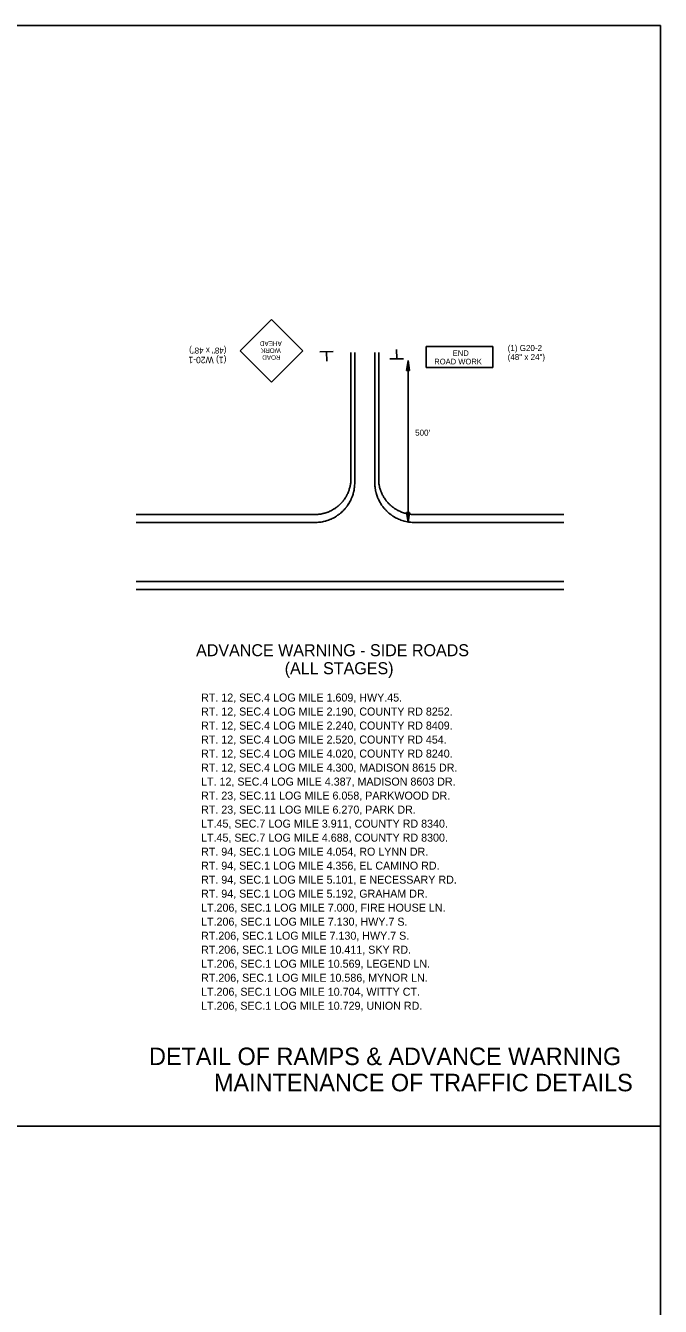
# Model space of a CAD drawing. Extents: x -100 to 745, y -1581 to -107.
# Drawn here: x 281.9 to 345.4, y -278.6 to -150.6 of the extents above; entities that cross this region are included whole.
import ezdxf

# ---------------------------------------------------------------- set-up
doc = ezdxf.new("R2010")
doc.units = 0
for name, color, linetype in [('Default', 7, 'Continuous'), ('R_Contour Annot', 7, 'Continuous'), ('R_Draft', 7, 'Continuous')]:
    doc.layers.add(name, color=color, linetype=linetype)

msp = doc.modelspace()

# ---------------------------------------------------------------- linework, layer by layer
at = {"layer": 'Default'}
for p, q in [((303.41, -183.07), (306.53, -179.95)), ((306.53, -179.95), (309.66, -183.07)), ((319.05, -183.86), (319.04, -182.94)), ((328.64, -182.65), (321.99, -182.65)), ((321.99, -184.74), (321.99, -182.65)), ((328.64, -184.74), (328.64, -182.65)), ((303.41, -183.07), (306.53, -186.2)), ((306.53, -186.2), (309.66, -183.07)), ((311.36, -183.18), (312.71, -183.16)), ((312.04, -183.19), (312.05, -184.11)), ((314.45, -187.09), (314.45, -183.24)), ((314.85, -187.09), (314.85, -183.24)), ((316.85, -187.09), (316.85, -183.24)), ((317.25, -187.09), (317.25, -183.24)), ((319.72, -183.88), (318.37, -183.89)), ((320.03, -185.05), (320.18, -184.05)), ((320.06, -185.05), (320.18, -184.22)), ((320.18, -184.05), (320.18, -200.24)), ((320.33, -185.05), (320.18, -184.05)), ((320.31, -185.05), (320.18, -184.22)), ((320.03, -185.05), (320.33, -185.05)), ((320.08, -185.05), (320.18, -184.39)), ((320.11, -185.05), (320.18, -184.55)), ((320.13, -185.05), (320.18, -184.72)), ((320.16, -185.05), (320.18, -184.89)), ((320.28, -185.05), (320.18, -184.39)), ((320.26, -185.05), (320.18, -184.55)), ((320.23, -185.05), (320.18, -184.72)), ((320.21, -185.05), (320.18, -184.89)), ((328.64, -184.74), (321.99, -184.74)), ((320.03, -199.24), (320.18, -200.24)), ((320.03, -199.24), (320.33, -199.24)), ((320.06, -199.24), (320.18, -200.07)), ((320.08, -199.24), (320.18, -199.9)), ((320.11, -199.24), (320.18, -199.73)), ((320.13, -199.24), (320.18, -199.57)), ((320.16, -199.24), (320.18, -199.4)), ((320.33, -199.24), (320.18, -200.24)), ((320.23, -199.24), (320.18, -199.57)), ((320.28, -199.24), (320.18, -199.9)), ((320.31, -199.24), (320.18, -200.07)), ((320.26, -199.24), (320.18, -199.73)), ((320.21, -199.24), (320.18, -199.4))]:
    msp.add_line(p, q, dxfattribs=at)
for points in [[(310.85, -200.24), (310.98, -200.24), (311.11, -200.23), (311.24, -200.22), (311.36, -200.21), (311.48, -200.19), (311.49, -200.19), (311.62, -200.17), (311.74, -200.14), (311.87, -200.11), (311.94, -200.09), (311.99, -200.08), (312.11, -200.04), (312.23, -199.99), (312.24, -199.99), (312.35, -199.95), (312.47, -199.9), (312.49, -199.89), (312.59, -199.84), (312.7, -199.79), (312.7, -199.79), (312.82, -199.73), (312.88, -199.69), (312.93, -199.66), (313.03, -199.59), (313.04, -199.59), (313.14, -199.52), (313.18, -199.49), (313.24, -199.45), (313.32, -199.39), (313.35, -199.37), (313.44, -199.29), (313.45, -199.29), (313.54, -199.2), (313.55, -199.19), (313.63, -199.11), (313.66, -199.09), (313.68, -199.07), (313.73, -199.02), (313.76, -198.99), (313.81, -198.93), (313.85, -198.89), (313.9, -198.83), (313.93, -198.79), (313.98, -198.73), (314.01, -198.69), (314.06, -198.63), (314.09, -198.59), (314.13, -198.53), (314.16, -198.49), (314.2, -198.42), (314.23, -198.39), (314.27, -198.31), (314.29, -198.29), (314.32, -198.24), (314.34, -198.2), (314.34, -198.19), (314.4, -198.09), (314.4, -198.09), (314.45, -197.99), (314.46, -197.98), (314.5, -197.89), (314.51, -197.86), (314.54, -197.79), (314.56, -197.74), (314.58, -197.69), (314.61, -197.62), (314.62, -197.59), (314.65, -197.5), (314.65, -197.49), (314.68, -197.39), (314.69, -197.38), (314.71, -197.29), (314.72, -197.25), (314.74, -197.19), (314.75, -197.13), (314.76, -197.09), (314.78, -197), (314.78, -196.99), (314.8, -196.89), (314.8, -196.88), (314.81, -196.79), (314.82, -196.75), (314.83, -196.69), (314.83, -196.62), (314.84, -196.59), (314.84, -196.5), (314.84, -196.49), (314.85, -196.39), (314.85, -196.37), (314.85, -196.29), (314.85, -196.24), (314.85, -196.19), (314.85, -196.09), (314.85, -195.99), (314.85, -195.89), (314.85, -195.79), (314.85, -195.69), (314.85, -195.59), (314.85, -195.49), (314.85, -195.39), (314.85, -195.29), (314.85, -195.19), (314.85, -195.09), (314.85, -194.99), (314.85, -194.89), (314.85, -194.79), (314.85, -194.69), (314.85, -194.59), (314.85, -194.49), (314.85, -194.39), (314.85, -194.29), (314.85, -194.19), (314.85, -194.09), (314.85, -193.99), (314.85, -193.89), (314.85, -193.79), (314.85, -193.69), (314.85, -193.59), (314.85, -193.49), (314.85, -193.39), (314.85, -193.29), (314.85, -193.19), (314.85, -193.09), (314.85, -192.99), (314.85, -192.89), (314.85, -192.79), (314.85, -192.69), (314.85, -192.59), (314.85, -192.49), (314.85, -192.39), (314.85, -192.29), (314.85, -192.19), (314.85, -192.09), (314.85, -191.99), (314.85, -191.89), (314.85, -191.79), (314.85, -191.69), (314.85, -191.59), (314.85, -191.49), (314.85, -191.39), (314.85, -191.29), (314.85, -191.19), (314.85, -191.09), (314.85, -190.99), (314.85, -190.89), (314.85, -190.79), (314.85, -190.69), (314.85, -190.59), (314.85, -190.49), (314.85, -190.39), (314.85, -190.29), (314.85, -190.19), (314.85, -190.09), (314.85, -189.99), (314.85, -189.89), (314.85, -189.79), (314.85, -189.69), (314.85, -189.59), (314.85, -189.49), (314.85, -189.39), (314.85, -189.29), (314.85, -189.19), (314.85, -189.09), (314.85, -188.99), (314.85, -188.89), (314.85, -188.79), (314.85, -188.69), (314.85, -188.59), (314.85, -188.49), (314.85, -188.39), (314.85, -188.29), (314.85, -188.24), (314.85, -188.19), (314.85, -188.09), (314.85, -187.99), (314.85, -187.89), (314.85, -187.79), (314.85, -187.69), (314.85, -187.59), (314.85, -187.49), (314.85, -187.39), (314.85, -187.32), (314.85, -187.29), (314.85, -187.19), (314.85, -187.09)], [(310.85, -199.44), (310.95, -199.44), (311.06, -199.43), (311.16, -199.43), (311.26, -199.42), (311.36, -199.41), (311.36, -199.4), (311.47, -199.39), (311.57, -199.37), (311.67, -199.35), (311.72, -199.33), (311.77, -199.32), (311.87, -199.3), (311.97, -199.27), (311.97, -199.26), (312.06, -199.23), (312.16, -199.2), (312.18, -199.19), (312.26, -199.16), (312.35, -199.12), (312.35, -199.12), (312.45, -199.07), (312.5, -199.05), (312.54, -199.03), (312.63, -198.98), (312.64, -198.97), (312.72, -198.92), (312.76, -198.9), (312.81, -198.87), (312.88, -198.83), (312.9, -198.81), (312.98, -198.75), (312.99, -198.75), (313.07, -198.69), (313.08, -198.68), (313.16, -198.62), (313.18, -198.6), (313.2, -198.59), (313.24, -198.55), (313.27, -198.53), (313.32, -198.48), (313.35, -198.45), (313.4, -198.41), (313.43, -198.37), (313.47, -198.33), (313.5, -198.3), (313.55, -198.25), (313.58, -198.22), (313.62, -198.17), (313.64, -198.14), (313.69, -198.09), (313.71, -198.06), (313.75, -198), (313.77, -197.98), (313.8, -197.94), (313.82, -197.91), (313.83, -197.9), (313.88, -197.82), (313.88, -197.82), (313.93, -197.74), (313.94, -197.73), (313.98, -197.66), (314, -197.63), (314.03, -197.58), (314.05, -197.53), (314.07, -197.49), (314.1, -197.44), (314.11, -197.41), (314.15, -197.34), (314.15, -197.33), (314.19, -197.24), (314.19, -197.23), (314.22, -197.16), (314.24, -197.13), (314.26, -197.07), (314.28, -197.02), (314.29, -196.99), (314.31, -196.91), (314.31, -196.9), (314.34, -196.81), (314.34, -196.8), (314.36, -196.73), (314.37, -196.69), (314.38, -196.64), (314.4, -196.58), (314.4, -196.55), (314.42, -196.47), (314.42, -196.46), (314.43, -196.37), (314.44, -196.36), (314.45, -196.29), (314.45, -196.24), (314.45, -196.19), (314.45, -196.09), (314.45, -195.99), (314.45, -195.89), (314.45, -195.79), (314.45, -195.69), (314.45, -195.59), (314.45, -195.49), (314.45, -195.39), (314.45, -195.29), (314.45, -195.19), (314.45, -195.09), (314.45, -194.99), (314.45, -194.89), (314.45, -194.79), (314.45, -194.69), (314.45, -194.59), (314.45, -194.49), (314.45, -194.39), (314.45, -194.29), (314.45, -194.19), (314.45, -194.09), (314.45, -193.99), (314.45, -193.89), (314.45, -193.79), (314.45, -193.69), (314.45, -193.59), (314.45, -193.49), (314.45, -193.39), (314.45, -193.29), (314.45, -193.19), (314.45, -193.09), (314.45, -192.99), (314.45, -192.89), (314.45, -192.79), (314.45, -192.69), (314.45, -192.59), (314.45, -192.49), (314.45, -192.39), (314.45, -192.29), (314.45, -192.19), (314.45, -192.09), (314.45, -191.99), (314.45, -191.89), (314.45, -191.79), (314.45, -191.69), (314.45, -191.59), (314.45, -191.49), (314.45, -191.39), (314.45, -191.29), (314.45, -191.19), (314.45, -191.09), (314.45, -190.99), (314.45, -190.89), (314.45, -190.79), (314.45, -190.69), (314.45, -190.59), (314.45, -190.49), (314.45, -190.39), (314.45, -190.29), (314.45, -190.19), (314.45, -190.09), (314.45, -189.99), (314.45, -189.89), (314.45, -189.79), (314.45, -189.69), (314.45, -189.59), (314.45, -189.49), (314.45, -189.39), (314.45, -189.29), (314.45, -189.19), (314.45, -189.09), (314.45, -188.99), (314.45, -188.89), (314.45, -188.79), (314.45, -188.69), (314.45, -188.59), (314.45, -188.49), (314.45, -188.39), (314.45, -188.29), (314.45, -188.24), (314.45, -188.19), (314.45, -188.09), (314.45, -187.99), (314.45, -187.89), (314.45, -187.79), (314.45, -187.69), (314.45, -187.59), (314.45, -187.49), (314.45, -187.39), (314.45, -187.32), (314.45, -187.29), (314.45, -187.19), (314.45, -187.09)], [(320.85, -200.24), (320.72, -200.24), (320.6, -200.23), (320.47, -200.22), (320.34, -200.21), (320.22, -200.19), (320.21, -200.19), (320.09, -200.17), (319.96, -200.14), (319.84, -200.11), (319.77, -200.09), (319.71, -200.08), (319.59, -200.04), (319.47, -199.99), (319.46, -199.99), (319.35, -199.95), (319.23, -199.9), (319.22, -199.89), (319.12, -199.84), (319.01, -199.79), (319, -199.79), (318.89, -199.73), (318.83, -199.69), (318.78, -199.66), (318.67, -199.59), (318.67, -199.59), (318.56, -199.52), (318.52, -199.49), (318.46, -199.45), (318.39, -199.39), (318.36, -199.37), (318.26, -199.29), (318.26, -199.29), (318.16, -199.2), (318.15, -199.19), (318.07, -199.11), (318.05, -199.09), (318.02, -199.07), (317.98, -199.02), (317.95, -198.99), (317.89, -198.93), (317.86, -198.89), (317.81, -198.83), (317.77, -198.79), (317.72, -198.73), (317.69, -198.69), (317.65, -198.63), (317.62, -198.59), (317.57, -198.53), (317.54, -198.49), (317.5, -198.42), (317.48, -198.39), (317.43, -198.31), (317.42, -198.29), (317.39, -198.24), (317.37, -198.2), (317.36, -198.19), (317.31, -198.09), (317.31, -198.09), (317.26, -197.99), (317.25, -197.98), (317.21, -197.89), (317.19, -197.86), (317.16, -197.79), (317.14, -197.74), (317.12, -197.69), (317.1, -197.62), (317.09, -197.59), (317.06, -197.5), (317.05, -197.49), (317.02, -197.39), (317.02, -197.38), (316.99, -197.29), (316.98, -197.25), (316.97, -197.19), (316.95, -197.13), (316.94, -197.09), (316.93, -197), (316.92, -196.99), (316.91, -196.89), (316.9, -196.88), (316.89, -196.79), (316.89, -196.75), (316.88, -196.69), (316.87, -196.62), (316.87, -196.59), (316.86, -196.5), (316.86, -196.49), (316.85, -196.39), (316.85, -196.37), (316.85, -196.29), (316.85, -196.24), (316.85, -196.19), (316.85, -196.09), (316.85, -195.99), (316.85, -195.89), (316.85, -195.79), (316.85, -195.69), (316.85, -195.59), (316.85, -195.49), (316.85, -195.39), (316.85, -195.29), (316.85, -195.19), (316.85, -195.09), (316.85, -194.99), (316.85, -194.89), (316.85, -194.79), (316.85, -194.69), (316.85, -194.59), (316.85, -194.49), (316.85, -194.39), (316.85, -194.29), (316.85, -194.19), (316.85, -194.09), (316.85, -193.99), (316.85, -193.89), (316.85, -193.79), (316.85, -193.69), (316.85, -193.59), (316.85, -193.49), (316.85, -193.39), (316.85, -193.29), (316.85, -193.19), (316.85, -193.09), (316.85, -192.99), (316.85, -192.89), (316.85, -192.79), (316.85, -192.69), (316.85, -192.59), (316.85, -192.49), (316.85, -192.39), (316.85, -192.29), (316.85, -192.19), (316.85, -192.09), (316.85, -191.99), (316.85, -191.89), (316.85, -191.79), (316.85, -191.69), (316.85, -191.59), (316.85, -191.49), (316.85, -191.39), (316.85, -191.29), (316.85, -191.19), (316.85, -191.09), (316.85, -190.99), (316.85, -190.89), (316.85, -190.79), (316.85, -190.69), (316.85, -190.59), (316.85, -190.49), (316.85, -190.39), (316.85, -190.29), (316.85, -190.19), (316.85, -190.09), (316.85, -189.99), (316.85, -189.89), (316.85, -189.79), (316.85, -189.69), (316.85, -189.59), (316.85, -189.49), (316.85, -189.39), (316.85, -189.29), (316.85, -189.19), (316.85, -189.09), (316.85, -188.99), (316.85, -188.89), (316.85, -188.79), (316.85, -188.69), (316.85, -188.59), (316.85, -188.49), (316.85, -188.39), (316.85, -188.29), (316.85, -188.24), (316.85, -188.19), (316.85, -188.09), (316.85, -187.99), (316.85, -187.89), (316.85, -187.79), (316.85, -187.69), (316.85, -187.59), (316.85, -187.49), (316.85, -187.39), (316.85, -187.32), (316.85, -187.29), (316.85, -187.19), (316.85, -187.09)], [(320.85, -199.44), (320.75, -199.44), (320.65, -199.43), (320.54, -199.43), (320.44, -199.42), (320.35, -199.41), (320.34, -199.4), (320.24, -199.39), (320.14, -199.37), (320.04, -199.35), (319.98, -199.33), (319.94, -199.32), (319.84, -199.3), (319.74, -199.27), (319.73, -199.26), (319.64, -199.23), (319.54, -199.2), (319.53, -199.19), (319.45, -199.16), (319.36, -199.12), (319.35, -199.12), (319.26, -199.07), (319.2, -199.05), (319.16, -199.03), (319.07, -198.98), (319.07, -198.97), (318.98, -198.92), (318.94, -198.9), (318.89, -198.87), (318.83, -198.83), (318.8, -198.81), (318.72, -198.75), (318.72, -198.75), (318.63, -198.69), (318.62, -198.68), (318.55, -198.62), (318.53, -198.6), (318.51, -198.59), (318.47, -198.55), (318.44, -198.53), (318.39, -198.48), (318.35, -198.45), (318.31, -198.41), (318.28, -198.37), (318.23, -198.33), (318.2, -198.3), (318.16, -198.25), (318.13, -198.22), (318.09, -198.17), (318.06, -198.14), (318.02, -198.09), (318, -198.06), (317.95, -198), (317.94, -197.98), (317.91, -197.94), (317.89, -197.91), (317.88, -197.9), (317.82, -197.82), (317.82, -197.82), (317.77, -197.74), (317.77, -197.73), (317.72, -197.66), (317.71, -197.63), (317.68, -197.58), (317.65, -197.53), (317.63, -197.49), (317.6, -197.44), (317.59, -197.41), (317.56, -197.34), (317.55, -197.33), (317.51, -197.24), (317.51, -197.23), (317.48, -197.16), (317.47, -197.13), (317.45, -197.07), (317.43, -197.02), (317.42, -196.99), (317.39, -196.91), (317.39, -196.9), (317.36, -196.81), (317.36, -196.8), (317.34, -196.73), (317.33, -196.69), (317.32, -196.64), (317.31, -196.58), (317.3, -196.55), (317.29, -196.47), (317.28, -196.46), (317.27, -196.37), (317.27, -196.36), (317.26, -196.29), (317.25, -196.24), (317.25, -196.19), (317.25, -196.09), (317.25, -195.99), (317.25, -195.89), (317.25, -195.79), (317.25, -195.69), (317.25, -195.59), (317.25, -195.49), (317.25, -195.39), (317.25, -195.29), (317.25, -195.19), (317.25, -195.09), (317.25, -194.99), (317.25, -194.89), (317.25, -194.79), (317.25, -194.69), (317.25, -194.59), (317.25, -194.49), (317.25, -194.39), (317.25, -194.29), (317.25, -194.19), (317.25, -194.09), (317.25, -193.99), (317.25, -193.89), (317.25, -193.79), (317.25, -193.69), (317.25, -193.59), (317.25, -193.49), (317.25, -193.39), (317.25, -193.29), (317.25, -193.19), (317.25, -193.09), (317.25, -192.99), (317.25, -192.89), (317.25, -192.79), (317.25, -192.69), (317.25, -192.59), (317.25, -192.49), (317.25, -192.39), (317.25, -192.29), (317.25, -192.19), (317.25, -192.09), (317.25, -191.99), (317.25, -191.89), (317.25, -191.79), (317.25, -191.69), (317.25, -191.59), (317.25, -191.49), (317.25, -191.39), (317.25, -191.29), (317.25, -191.19), (317.25, -191.09), (317.25, -190.99), (317.25, -190.89), (317.25, -190.79), (317.25, -190.69), (317.25, -190.59), (317.25, -190.49), (317.25, -190.39), (317.25, -190.29), (317.25, -190.19), (317.25, -190.09), (317.25, -189.99), (317.25, -189.89), (317.25, -189.79), (317.25, -189.69), (317.25, -189.59), (317.25, -189.49), (317.25, -189.39), (317.25, -189.29), (317.25, -189.19), (317.25, -189.09), (317.25, -188.99), (317.25, -188.89), (317.25, -188.79), (317.25, -188.69), (317.25, -188.59), (317.25, -188.49), (317.25, -188.39), (317.25, -188.29), (317.25, -188.24), (317.25, -188.19), (317.25, -188.09), (317.25, -187.99), (317.25, -187.89), (317.25, -187.79), (317.25, -187.69), (317.25, -187.59), (317.25, -187.49), (317.25, -187.39), (317.25, -187.32), (317.25, -187.29), (317.25, -187.19), (317.25, -187.09), (317.25, -187.09)], [(310.85, -199.44), (310.35, -199.44), (309.35, -199.44), (308.35, -199.44), (307.35, -199.44), (306.35, -199.44), (305.35, -199.44), (304.55, -199.44), (304.35, -199.44), (303.35, -199.44), (302.35, -199.44), (301.35, -199.44), (300.35, -199.44), (299.35, -199.44), (298.35, -199.44), (297.35, -199.44), (297.23, -199.44), (296.35, -199.44), (295.35, -199.44), (294.35, -199.44), (293.35, -199.44), (293, -199.44)], [(335.74, -199.44), (335.35, -199.44), (334.35, -199.44), (333.35, -199.44), (332.35, -199.44), (331.35, -199.44), (330.35, -199.44), (329.35, -199.44), (328.35, -199.44), (327.35, -199.44), (326.53, -199.44), (326.53, -199.44), (326.35, -199.44), (325.35, -199.44), (324.35, -199.44), (323.35, -199.44), (322.35, -199.44), (321.35, -199.44), (320.85, -199.44)], [(310.85, -200.24), (310.35, -200.24), (309.35, -200.24), (308.35, -200.24), (307.35, -200.24), (306.35, -200.24), (305.35, -200.24), (304.55, -200.24), (304.35, -200.24), (303.35, -200.24), (302.35, -200.24), (301.35, -200.24), (300.35, -200.24), (299.35, -200.24), (298.35, -200.24), (297.35, -200.24), (297.23, -200.24), (296.35, -200.24), (295.35, -200.24), (294.35, -200.24), (293.35, -200.24), (293, -200.24)], [(335.74, -200.24), (335.35, -200.24), (334.35, -200.24), (333.35, -200.24), (332.35, -200.24), (331.35, -200.24), (330.35, -200.24), (329.35, -200.24), (328.35, -200.24), (327.35, -200.24), (326.53, -200.24), (326.53, -200.24), (326.35, -200.24), (325.35, -200.24), (324.35, -200.24), (323.35, -200.24), (322.35, -200.24), (321.35, -200.24), (320.85, -200.24)], [(335.74, -206.14), (334.35, -206.14), (333.35, -206.14), (332.35, -206.14), (331.35, -206.14), (330.35, -206.14), (329.35, -206.14), (328.35, -206.14), (327.35, -206.14), (326.53, -206.14), (326.53, -206.14), (326.35, -206.14), (325.35, -206.14), (324.35, -206.14), (323.35, -206.14), (322.35, -206.14), (321.35, -206.14), (320.35, -206.14), (319.35, -206.14), (318.35, -206.14), (317.35, -206.14), (316.35, -206.14), (315.85, -206.14), (315.35, -206.14), (314.35, -206.14), (313.35, -206.14), (312.35, -206.14), (311.88, -206.14), (311.88, -206.14), (311.35, -206.14), (310.35, -206.14), (309.35, -206.14), (308.35, -206.14), (307.35, -206.14), (306.35, -206.14), (305.35, -206.14), (304.55, -206.14), (304.35, -206.14), (303.35, -206.14), (302.35, -206.14), (301.35, -206.14), (300.35, -206.14), (299.35, -206.14), (298.35, -206.14), (297.35, -206.14), (297.23, -206.14), (296.35, -206.14), (295.35, -206.14), (294.35, -206.14), (293.35, -206.14), (293, -206.14)], [(335.74, -206.94), (334.35, -206.94), (333.35, -206.94), (332.35, -206.94), (331.35, -206.94), (330.35, -206.94), (329.35, -206.94), (328.35, -206.94), (327.35, -206.94), (326.53, -206.94), (326.53, -206.94), (326.35, -206.94), (325.35, -206.94), (324.35, -206.94), (323.35, -206.94), (322.35, -206.94), (321.35, -206.94), (320.35, -206.94), (319.35, -206.94), (318.35, -206.94), (317.35, -206.94), (316.35, -206.94), (315.85, -206.94), (315.35, -206.94), (314.35, -206.94), (313.35, -206.94), (312.35, -206.94), (311.88, -206.94), (311.88, -206.94), (311.35, -206.94), (310.35, -206.94), (309.35, -206.94), (308.35, -206.94), (307.35, -206.94), (306.35, -206.94), (305.35, -206.94), (304.55, -206.94), (304.35, -206.94), (303.35, -206.94), (302.35, -206.94), (301.35, -206.94), (300.35, -206.94), (299.35, -206.94), (298.35, -206.94), (297.35, -206.94), (297.23, -206.94), (296.35, -206.94), (295.35, -206.94), (294.35, -206.94), (293.35, -206.94), (293, -206.94)]]:
    msp.add_lwpolyline(points, dxfattribs=at)
at = {"layer": 'R_Contour Annot'}
for points in [[(175.41, -150.58), (345.41, -150.58), (345.41, -260.58), (175.41, -260.58)], [(175.41, -260.58), (345.41, -260.58), (345.41, -370.58), (175.41, -370.58)]]:
    msp.add_lwpolyline(points, close=True, dxfattribs=at)
at = {"layer": 'R_Draft'}
for points in [[(175.41, -150.58), (175.41, -260.58), (345.41, -260.58), (345.41, -150.58)], [(175.41, -260.58), (175.41, -370.58), (345.41, -370.58), (345.41, -260.58)]]:
    msp.add_lwpolyline(points, close=True, dxfattribs=at)

# ---------------------------------------------------------------- texts
at = {"layer": 'Default'}
for s, height, rotation, p in [('(48" x 48")', 0.5999, 180, (302.03, -182.76)), ('AHEAD', 0.461, 180.0006, (307.56, -182.14)), ('WORK', 0.461, 180, (307.45, -182.83)), ('(1) W20-1', 0.64, 180, (302.03, -183.68)), ('ROAD', 0.461, 180.0004, (307.44, -183.52))]:
    msp.add_text(s, height=height, rotation=rotation, dxfattribs=at).set_placement(p)
for s, height, p in [('(1) G20-2', 0.6, (330.14, -183.1)), ('ROAD WORK', 0.567, (322.8, -184.44)), ('END', 0.567, (324.65, -183.6)), ('(48" x 24")', 0.5999, (330.14, -184)), ("500'", 0.6, (320.89, -191.56)), ('ADVANCE WARNING - SIDE ROADS', 1.2, (298.99, -213.6)), ('(ALL STAGES)', 1.2, (307.85, -215.4)), ('RT. 12, SEC.4 LOG MILE 1.609, HWY.45.', 0.8, (299.49, -218.13)), ('RT. 12, SEC.4 LOG MILE 2.190, COUNTY RD 8252.', 0.8, (299.49, -219.53)), ('RT. 12, SEC.4 LOG MILE 2.240, COUNTY RD 8409.', 0.8, (299.49, -220.93)), ('RT. 12, SEC.4 LOG MILE 2.520, COUNTY RD 454.', 0.8, (299.49, -222.33)), ('RT. 12, SEC.4 LOG MILE 4.020, COUNTY RD 8240.', 0.8, (299.49, -223.73)), ('RT. 12, SEC.4 LOG MILE 4.300, MADISON 8615 DR.', 0.8, (299.49, -225.13)), ('LT. 12, SEC.4 LOG MILE 4.387, MADISON 8603 DR.', 0.8, (299.49, -226.53)), ('RT. 23, SEC.11 LOG MILE 6.058, PARKWOOD DR.', 0.8, (299.49, -227.93)), ('RT. 23, SEC.11 LOG MILE 6.270, PARK DR.', 0.8, (299.49, -229.33)), ('LT.45, SEC.7 LOG MILE 3.911, COUNTY RD 8340.', 0.8, (299.49, -230.73)), ('LT.45, SEC.7 LOG MILE 4.688, COUNTY RD 8300.', 0.8, (299.49, -232.13)), ('RT. 94, SEC.1 LOG MILE 4.054, RO LYNN DR.', 0.8, (299.49, -233.53)), ('RT. 94, SEC.1 LOG MILE 4.356, EL CAMINO RD.', 0.8, (299.49, -234.93)), ('RT. 94, SEC.1 LOG MILE 5.101, E NECESSARY RD.', 0.8, (299.49, -236.33)), ('RT. 94, SEC.1 LOG MILE 5.192, GRAHAM DR.', 0.8, (299.49, -237.73)), ('LT.206, SEC.1 LOG MILE 7.000, FIRE HOUSE LN.', 0.8, (299.49, -239.13)), ('LT.206, SEC.1 LOG MILE 7.130, HWY.7 S.', 0.8, (299.49, -240.53)), ('RT.206, SEC.1 LOG MILE 7.130, HWY.7 S.', 0.8, (299.49, -241.93)), ('RT.206, SEC.1 LOG MILE 10.411, SKY RD.', 0.8, (299.49, -243.33)), ('LT.206, SEC.1 LOG MILE 10.569, LEGEND LN.', 0.8, (299.49, -244.73)), ('RT.206, SEC.1 LOG MILE 10.586, MYNOR LN.', 0.8, (299.49, -246.13)), ('LT.206, SEC.1 LOG MILE 10.704, WITTY CT.', 0.8, (299.49, -247.53)), ('LT.206, SEC.1 LOG MILE 10.729, UNION RD.', 0.8, (299.49, -248.93)), ('DETAIL OF RAMPS & ADVANCE WARNING', 1.75, (294.29, -254.46)), ('MAINTENANCE OF TRAFFIC DETAILS', 1.75, (300.78, -257.08))]:
    msp.add_text(s, height=height, dxfattribs=at).set_placement(p)

doc.saveas('drawing.dxf')
